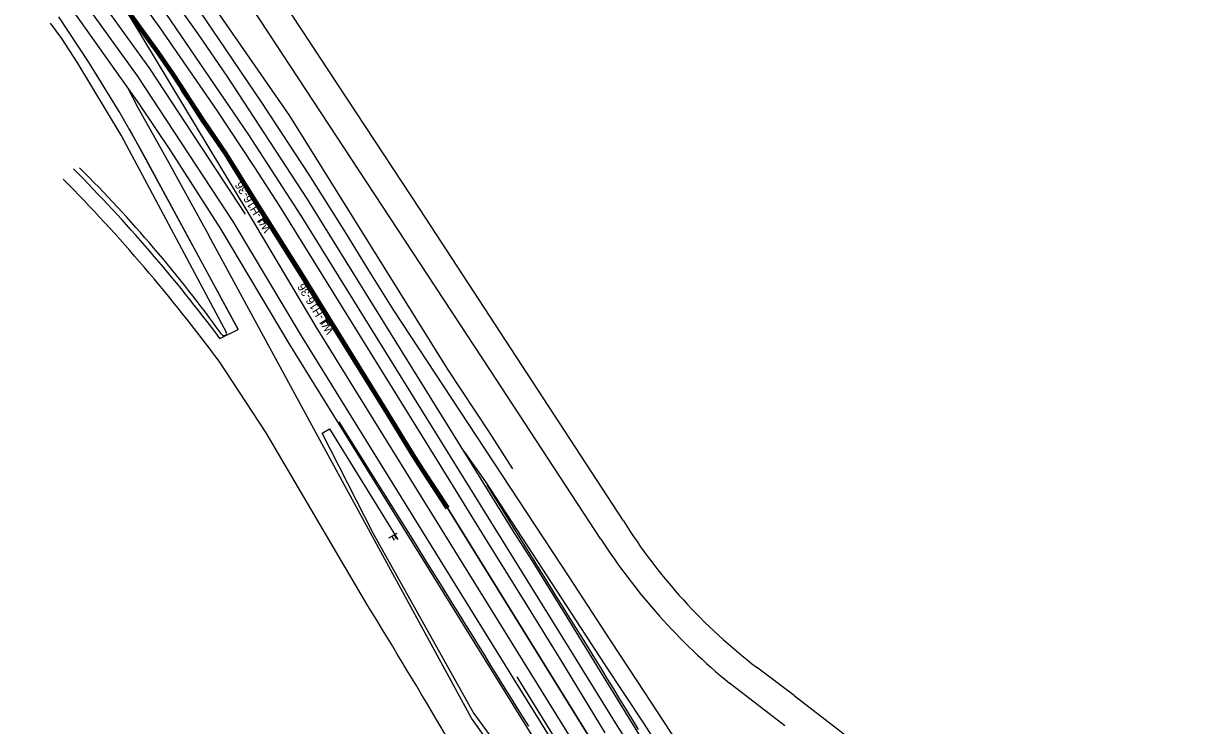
# Model space of a CAD drawing. Extents: x 1691089 to 1704871, y 694247 to 736350.
# Drawn here: x 1696714 to 1697688, y 719881 to 720467 of the extents above; entities that cross this region are included whole.
import ezdxf

# ---------------------------------------------------------------- set-up
doc = ezdxf.new("R2010")
doc.units = 0
for name, color, linetype in [('MT_P_Drums', 7, 'Continuous'), ('MT_P_Edge_Line', 7, 'Continuous'), ('PM_P_Channelizing_Line', 7, 'Continuous'), ('PM_X_Channelizing_Line', 7, 'Continuous'), ('PM_X_Edge_Line', 7, 'Continuous'), ('PM_X_Lane_Line', 7, 'Continuous'), ('PV_X_EOP', 7, 'Continuous'), ('PV_X_Shoulder', 7, 'Continuous'), ('PV_X_Shoulder_Rumble_Strip', 7, 'Continuous'), ('RD_X_Concrete_Barrier', 7, 'Continuous'), ('RW_X_CL', 7, 'Continuous'), ('SC_Scratch1', 7, 'Continuous'), ('SC_Scratch2', 7, 'Continuous'), ('SN_P_Signs', 7, 'Continuous')]:
    doc.layers.add(name, color=color, linetype=linetype)

msp = doc.modelspace()

# ---------------------------------------------------------------- linework, layer by layer
at = {"layer": 'MT_P_Drums'}
for p, q in [((1696901.4, 720309.12), (1696803.07, 720472.64)), ((1696958.31, 720213.74), (1696901.37, 720309.16)), ((1697302.58, 719657.96), (1696958.29, 720213.77)), ((1697319.24, 719609.23), (1697125.87, 719921.39))]:
    msp.add_line(p, q, dxfattribs=at)
at = {"layer": 'MT_P_Edge_Line'}
for p, q in [((1696945.96, 720206.14), (1696888.92, 720301.73)), ((1697123.32, 719919.81), (1696945.96, 720206.14)), ((1697316.69, 719607.65), (1697123.32, 719919.81))]:
    msp.add_line(p, q, dxfattribs=at)
for points in [[(1696888.92, 720301.73), (1696809.01, 720423.31), (1696762.81, 720487.7)], [(1697306.42, 719601.45), (1696935.76, 720199.82), (1696878.62, 720295.59)], [(1697364.72, 719636.45), (1697337.86, 719679.81), (1697209.39, 719880.95)]]:
    msp.add_lwpolyline(points, dxfattribs=at)
at = {"layer": 'PM_P_Channelizing_Line'}
msp.add_lwpolyline([(1696910.17, 720315.43), (1696907.11, 720320.18), (1696867.4, 720381.73), (1696850.41, 720407.51), (1696799.96, 720481.58), (1696695.84, 720618.66), (1696638.28, 720693.3), (1696578.4, 720765.83), (1696308.36, 721066.11), (1696204.27, 721188.35), (1696124.87, 721288.57), (1696069.86, 721373.83), (1696004.15, 721483.93), (1695952.81, 721586.67), (1695915.12, 721673.18)], dxfattribs=at)
at = {"layer": 'PM_X_Channelizing_Line'}
for points in [[(1696878.62, 720295.59), (1696836.97, 720360.85), (1696810.67, 720399.58), (1696753.42, 720480.4)], [(1696800.69, 720413.67), (1696809.28, 720396.97), (1696833.94, 720353.33), (1696850.55, 720322.93), (1696868.77, 720290.12)], [(1697232.86, 719865.21), (1697185.73, 719941.84), (1697169.86, 719967.64), (1697138.56, 720018.53), (1697123.5, 720041.98), (1697081.42, 720110.02)], [(1697081.42, 720110.02), (1697099.45, 720084.33), (1697138.64, 720024.22), (1697199.17, 719931.4), (1697230.83, 719883.55), (1697252.64, 719849.99), (1697267.64, 719826.9), (1697287.04, 719799.65), (1697295.97, 719787.12), (1697318.59, 719756.99), (1697332.74, 719738.65), (1697347.52, 719719.8)]]:
    msp.add_lwpolyline(points, dxfattribs=at)
at = {"layer": 'PM_X_Edge_Line'}
for points in [[(1696793.3, 720511.38), (1696827.73, 720463.52), (1696874.84, 720395.16), (1696906.71, 720346.84), (1696927.56, 720314.43), (1697062.36, 720097.04), (1697098.51, 720038.49), (1697133.87, 719981.66), (1697162.24, 719935.74), (1697199.26, 719874.79)], [(1696899.23, 720307.88), (1696819.32, 720429.45), (1696772.26, 720495.04)]]:
    msp.add_lwpolyline(points, dxfattribs=at)
at = {"layer": 'PM_X_Lane_Line'}
for points in [[(1697209.39, 719880.95), (1697169.42, 719945.82), (1696946.02, 720306.12), (1696902.03, 720374.01), (1696824.98, 720487.27), (1696802.49, 720518.52)], [(1697081.42, 720110.02), (1696950.85, 720320.3), (1696884.57, 720422.35), (1696859.81, 720458.46), (1696811.91, 720525.84)]]:
    msp.add_lwpolyline(points, dxfattribs=at)
at = {"layer": 'PV_X_EOP'}
for p, q in [((1696802.23, 720379.21), (1696893.09, 720211.57)), ((1696910.47, 720314.97), (1696910.47, 720314.97)), ((1697214.62, 720051.72), (1697045.11, 720311.79)), ((1696893.09, 720211.57), (1696854.37, 720283.01)), ((1696936.4, 720274.79), (1697955.64, 718629.38)), ((1696936.4, 720274.79), (1697955.64, 718629.38)), ((1696936.4, 720274.79), (1697955.64, 718629.38)), ((1696936.4, 720274.79), (1697955.64, 718629.38)), ((1696877.85, 720204.14), (1696893.09, 720211.57)), ((1696916.62, 720125.16), (1696877.19, 720184.95)), ((1697195.82, 720036.53), (1697103.13, 720178.06)), ((1697001.35, 719980.76), (1696916.62, 720125.16)), ((1697357.22, 719905.91), (1697325.73, 719929.44)), ((1697349.41, 719880.68), (1697303.2, 719916.17)), ((1697357.22, 719905.91), (1697421.7, 719856.1)), ((1697109.8, 719856.33), (1697087.91, 719886.93))]:
    msp.add_line(p, q, dxfattribs=at)
for points in [[(1697045.11, 720311.79), (1696914.96, 720509.51), (1696873.17, 720573.43)], [(1697103.13, 720178.06), (1696904.78, 720480.27), (1696853.77, 720558.36)], [(1697359.22, 719730.42), (1697341.01, 719753.22), (1697308.29, 719796.02), (1697294.54, 719815.3), (1697286.48, 719827.26), (1697275.51, 719843.07), (1697259.47, 719867.17), (1697226.75, 719917.42), (1697204.26, 719951.47), (1697169.51, 720004.98), (1697022.9, 720228.07), (1697002.02, 720261.28), (1696982.85, 720292.25), (1696952.2, 720341.27), (1696912.93, 720401.21), (1696877.35, 720453.78), (1696857.65, 720482.42), (1696834.73, 720515.16), (1696821.54, 720533.32)], [(1696854.37, 720283.01), (1696812.43, 720360.81), (1696793.91, 720393.54), (1696768.81, 720434.36), (1696743.46, 720472.66)], [(1697087.91, 719886.93), (1696959.94, 720121.88), (1696868.77, 720290.12)]]:
    msp.add_lwpolyline(points, dxfattribs=at)
for centre, radius, start, end in [((1695825.86, 719419.06), 1312.64, 36.7331, 44.89747), ((1695745.86, 719349.98), 1406.09, 36.42909, 44.59347), ((1697612.06, 720301.25), 469.28, 212.12221, 232.39995), ((1697635.6, 720320.82), 523.66, 212.88013, 230.59882), ((1690919.55, 716242.81), 7138.66, 30.566181, 31.575476)]:
    msp.add_arc(centre, radius, start, end, dxfattribs=at)
at = {"layer": 'PV_X_Shoulder'}
for p, q in [((1696963.33, 720125.01), (1696969.36, 720128.65)), ((1696969.36, 720128.65), (1697026.37, 720036.26)), ((1697006.12, 720040.94), (1696963.33, 720125.01)), ((1697089.18, 719891.85), (1697006.12, 720040.94)), ((1697114.15, 719858.03), (1697089.18, 719891.85))]:
    msp.add_line(p, q, dxfattribs=at)
for points in [[(1697122.43, 720095.22), (1697102.68, 720126.08), (1697068.52, 720177.96), (1696936.17, 720389.88), (1696845.05, 720521.88), (1696831.38, 720540.96)], [(1696846.47, 720410.15), (1696843.53, 720415.06), (1696837.17, 720424.71), (1696825.52, 720441.78), (1696794.73, 720484.09), (1696786.16, 720497.75), (1696782.37, 720502.89)], [(1696848.82, 720411.59), (1696845.88, 720416.5), (1696839.52, 720426.16), (1696827.87, 720443.23), (1696797.09, 720485.54), (1696788.51, 720499.19), (1696784.54, 720504.58)], [(1696883.68, 720208.55), (1696795.33, 720373.71), (1696758.69, 720434.66), (1696745.86, 720454.44), (1696736.45, 720467.22)], [(1697069.19, 720063.1), (1697048.19, 720095.14), (1697039.3, 720109.04), (1697019.25, 720141.86), (1696947.05, 720258.45), (1696907.82, 720320.74), (1696883.95, 720359.03), (1696864.98, 720386.86), (1696853.92, 720403.78), (1696848.82, 720411.59)], [(1697066.82, 720061.68), (1697045.82, 720093.72), (1697036.93, 720107.62), (1697016.88, 720140.44), (1696944.68, 720257.03), (1696905.45, 720319.32), (1696881.58, 720357.61), (1696862.61, 720385.44), (1696851.55, 720402.37), (1696846.47, 720410.15)]]:
    msp.add_lwpolyline(points, dxfattribs=at)
for centre, radius, start, end in [((1695965.09, 719547.72), 1127.42, 35.81767, 45.11907), ((1696881.28, 720208.92), 2.43, 215.73589, 351.21274)]:
    msp.add_arc(centre, radius, start, end, dxfattribs=at)
at = {"layer": 'PV_X_Shoulder_Rumble_Strip'}
for points in [[(1697135.67, 719880.15), (1697130.44, 719888.59), (1697125.14, 719897.05), (1697119.78, 719905.47), (1697114.54, 719913.98), (1697109.3, 719922.45), (1697104.04, 719930.95), (1697098.87, 719939.5), (1697093.62, 719948.02), (1697088.37, 719956.47), (1697083.07, 719964.96), (1697077.81, 719973.47), (1697072.56, 719981.97), (1697067.3, 719990.49), (1697062.02, 719999.01), (1697056.76, 720007.5), (1697051.5, 720015.95), (1697046.24, 720024.35), (1697041.02, 720032.84), (1696977.49, 720134.4)], [(1697227.24, 719877.39), (1697222.11, 719885.92), (1697216.92, 719894.36), (1697211.71, 719902.91), (1697206.55, 719911.38), (1697201.23, 719920.02), (1697196.03, 719928.58), (1697190.83, 719937.08), (1697185.63, 719945.58), (1697180.32, 719954.19), (1697174.97, 719962.71), (1697169.72, 719971.15), (1697164.44, 719979.55), (1697159.12, 719988.13), (1697153.84, 719996.54), (1697148.58, 720005.13), (1697143.27, 720013.53), (1697138, 720022.13), (1697132.69, 720030.55), (1697127.29, 720039.14), (1697122.06, 720047.68), (1697116.78, 720056.23), (1697111.47, 720064.72), (1697106.25, 720073.08), (1697100.99, 720081.68)]]:
    msp.add_lwpolyline(points, dxfattribs=at)
at = {"layer": 'RD_X_Concrete_Barrier'}
for points in [[(1696847.2, 720410.6), (1696844.26, 720415.51), (1696837.91, 720425.16), (1696826.25, 720442.24), (1696795.47, 720484.55), (1696786.89, 720498.2), (1696783.05, 720503.42)], [(1696848.05, 720411.12), (1696845.12, 720416.03), (1696838.76, 720425.69), (1696827.11, 720442.76), (1696796.32, 720485.07), (1696787.74, 720498.72), (1696783.83, 720504.03)], [(1697067.64, 720062.01), (1697046.64, 720094.05), (1697037.75, 720107.95), (1697017.7, 720140.78), (1696945.5, 720257.36), (1696906.26, 720319.65), (1696882.4, 720357.94), (1696863.43, 720385.77), (1696852.37, 720402.7), (1696847.2, 720410.6)], [(1697068.49, 720062.53), (1697047.49, 720094.57), (1697038.6, 720108.48), (1697018.55, 720141.3), (1696946.35, 720257.89), (1696907.11, 720320.18), (1696883.25, 720358.47), (1696864.28, 720386.3), (1696853.22, 720403.22), (1696848.05, 720411.12)]]:
    msp.add_lwpolyline(points, dxfattribs=at)
at = {"layer": 'RW_X_CL'}
msp.add_line((1697955.64, 718629.38), (1696936.4, 720274.79), dxfattribs=at)
at = {"layer": 'SC_Scratch2'}
msp.add_line((1696936.4, 720274.73), (1696910.47, 720314.97), dxfattribs=at)
msp.add_lwpolyline([(1696936.4, 720274.73), (1696910.47, 720314.97), (1696907.11, 720320.18), (1696867.4, 720381.73), (1696850.41, 720407.51), (1696799.96, 720481.58), (1696695.84, 720618.66), (1696638.28, 720693.3), (1696578.4, 720765.83), (1696308.36, 721066.11), (1696204.27, 721188.35), (1696124.87, 721288.57), (1696069.86, 721373.83), (1696004.15, 721483.93), (1695952.81, 721586.67), (1695915.12, 721673.18)], dxfattribs=at)
at = {"layer": 'SN_P_Signs'}
for p, q in [((1696910.07, 720301.54), (1696916.87, 720305.75)), ((1696913.47, 720303.64), (1696915.58, 720300.24)), ((1696962.96, 720216.67), (1696969.76, 720220.88)), ((1696966.36, 720218.78), (1696968.47, 720215.37)), ((1697018.84, 720037.62), (1697025.83, 720041.53)), ((1697021.29, 720038.99), (1697023.24, 720035.5)), ((1697022.33, 720039.58), (1697022.33, 720039.58)), ((1697022.33, 720039.58), (1697022.33, 720039.58)), ((1697023.38, 720040.16), (1697025.34, 720036.67))]:
    msp.add_line(p, q, dxfattribs=at)

# ---------------------------------------------------------------- texts
at = {"layer": 'SC_Scratch1'}
for p in [(1696921.08, 720295.24), (1696973.2, 720210.27)]:
    msp.add_text('W1-H16-36', height=7, rotation=121.77598, dxfattribs=at).set_placement(p)

doc.saveas('drawing.dxf')
